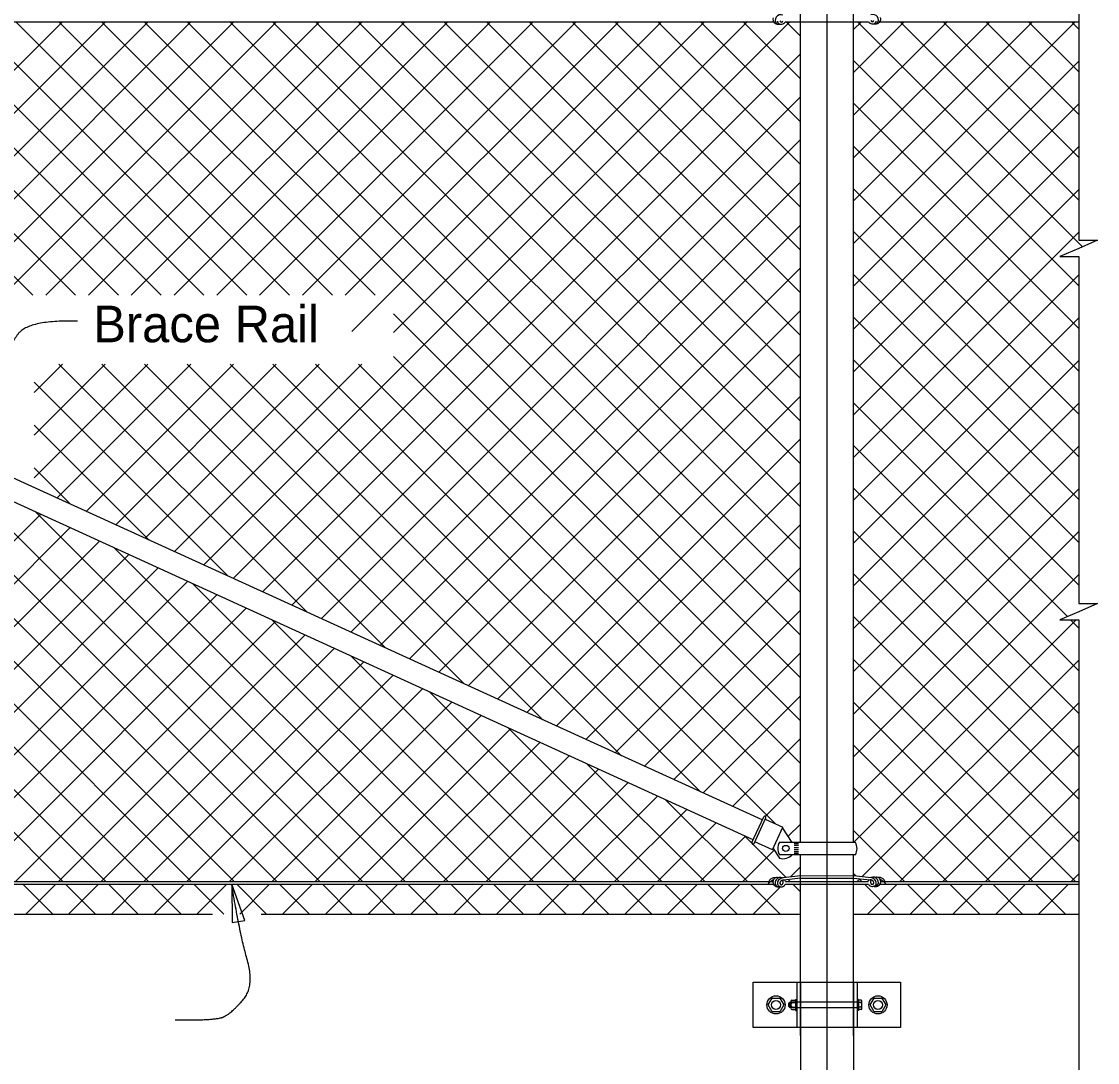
# Model space of a CAD drawing. Extents: x 0 to 41, y -96 to 25.
# Drawn here: x 10.89 to 16.81, y 14.82 to 20.56 of the extents above; entities that cross this region are included whole.
import ezdxf

# ---------------------------------------------------------------- set-up
doc = ezdxf.new("R2010")
doc.units = 0
for name, color, linetype in [('CL_Major', 7, 'Continuous'), ('Dimension', 7, 'Continuous'), ('Miscellaneous', 7, 'Continuous'), ('SteelMisc', 7, 'Continuous'), ('SteelMisc_h', 7, 'Continuous'), ('SupstrConc', 7, 'Continuous'), ('TextStructures', 7, 'Continuous')]:
    doc.layers.add(name, color=color, linetype=linetype)

msp = doc.modelspace()

# ---------------------------------------------------------------- linework, layer by layer
at = {"layer": 'CL_Major'}
msp.add_line((15.3237, 24.2317), (15.3237, 12.9956), dxfattribs=at)
at = {"layer": 'Dimension'}
for points in [[(16.7107, 22.5773), (16.7107, 19.3509), (16.814, 19.3509), (16.7107, 19.3059), (16.6074, 19.2609), (16.7107, 19.2609), (16.7107, 18.3673)], [(16.7107, 18.3673), (16.7107, 17.3495), (16.814, 17.3495), (16.7107, 17.3045), (16.6074, 17.2595), (16.7107, 17.2595), (16.7107, 15.0552)], [(16.7107, 15.3052), (16.7107, 13.4544), (16.814, 13.4544), (16.7107, 13.4094), (16.6074, 13.3644), (16.7107, 13.3644), (16.7107, 11.3636)]]:
    msp.add_lwpolyline(points, dxfattribs=at)
msp.add_lwpolyline([(12.0447, 15.8029), (12.0463, 15.5917), (12.1158, 15.604)], close=True, dxfattribs=at)
for points in [[(11.1949, 18.9047), (10.9254, 18.9129), (10.8073, 18.7544), (10.8043, 18.6333), (10.809, 18.4655), (10.817, 18.0525)], [(11.7334, 15.056), (11.9563, 15.0524), (12.0412, 15.0914), (12.172, 15.2401), (12.0871, 15.5375), (12.0447, 15.8029)]]:
    msp.add_open_spline(points, degree=2, dxfattribs=at)
at = {"layer": 'Miscellaneous'}
for p, q in [((9.3021, 18.7443), (11.113, 20.5552)), ((9.4413, 20.5552), (10.9489, 19.0476)), ((9.4639, 18.6704), (11.3487, 20.5552)), ((9.6257, 18.5965), (11.5844, 20.5552)), ((9.677, 20.5552), (11.1846, 19.0476)), ((9.7875, 18.5226), (11.8201, 20.5552)), ((9.9127, 20.5552), (11.4203, 19.0476)), ((9.9493, 18.4487), (12.0558, 20.5552)), ((10.1111, 18.3748), (12.2915, 20.5552)), ((10.1484, 20.5552), (11.656, 19.0476)), ((10.3841, 20.5552), (11.8917, 19.0476)), ((10.6198, 20.5552), (12.1274, 19.0476)), ((10.8555, 20.5552), (12.3631, 19.0476)), ((11.0197, 19.0476), (12.5272, 20.5552)), ((11.0912, 20.5552), (12.5988, 19.0476)), ((11.2554, 19.0476), (12.7629, 20.5552)), ((11.327, 20.5552), (12.8345, 19.0476)), ((11.4911, 19.0476), (12.9986, 20.5552)), ((11.5627, 20.5552), (13.26, 18.8579)), ((11.7268, 19.0476), (13.2343, 20.5552)), ((11.7984, 20.5552), (15.1779, 17.1756)), ((11.9625, 19.0476), (13.47, 20.5552)), ((12.0341, 20.5552), (15.1779, 17.4113)), ((12.1982, 19.0476), (13.7057, 20.5552)), ((12.2698, 20.5552), (15.1779, 17.6471)), ((12.4339, 19.0476), (13.9414, 20.5552)), ((12.5055, 20.5552), (15.1779, 17.8828)), ((12.6696, 19.0476), (14.1771, 20.5552)), ((12.706, 18.8484), (14.4129, 20.5552)), ((12.7412, 20.5552), (15.1779, 18.1185)), ((12.752, 18.1873), (15.12, 20.5552)), ((12.9357, 18.8424), (14.6486, 20.5552)), ((12.9769, 20.5552), (15.1779, 18.3542)), ((12.9878, 18.6587), (14.8843, 20.5552)), ((13.2126, 20.5552), (15.1779, 18.5899)), ((13.4483, 20.5552), (15.1779, 18.8256)), ((13.684, 20.5552), (15.1779, 19.0613)), ((13.9197, 20.5552), (15.1779, 19.297)), ((14.1554, 20.5552), (15.1779, 19.5327)), ((14.3911, 20.5552), (15.1779, 19.7684)), ((14.6268, 20.5552), (15.1779, 20.0041)), ((14.8625, 20.5552), (15.1779, 20.2398)), ((15.0982, 20.5552), (15.1779, 20.4755)), ((15.4696, 20.5115), (15.5133, 20.5552)), ((15.4696, 19.5686), (16.4561, 20.5552)), ((15.4696, 19.8043), (16.2204, 20.5552)), ((15.4696, 19.3329), (16.6918, 20.5552)), ((15.4696, 20.2758), (15.749, 20.5552)), ((15.4696, 20.0396), (15.9852, 20.5552)), ((15.4916, 20.5552), (16.7317, 19.315)), ((15.7273, 20.5552), (16.7107, 19.5718)), ((15.963, 20.5552), (16.7107, 19.8075)), ((16.1987, 20.5552), (16.7107, 20.0432)), ((16.4344, 20.5552), (16.7107, 20.2789)), ((16.6701, 20.5552), (16.7107, 20.5146)), ((12.9878, 18.1873), (15.1779, 20.3775)), ((15.4696, 20.3415), (16.7107, 19.1004)), ((15.4696, 19.0972), (16.7107, 20.3383)), ((13.2098, 18.1736), (15.1779, 20.1418)), ((15.4696, 20.1058), (16.7107, 18.8647)), ((15.4696, 18.8615), (16.7107, 20.1026)), ((13.4592, 18.1873), (15.1779, 19.9061)), ((15.4696, 19.8701), (16.7107, 18.629)), ((15.4696, 18.6258), (16.7107, 19.8669)), ((13.4803, 17.9727), (15.1779, 19.6704)), ((15.4696, 19.6344), (16.7107, 18.3933)), ((15.4696, 18.3901), (16.7107, 19.6312)), ((12.8619, 17.1187), (15.1779, 19.4347)), ((15.4696, 19.3987), (16.7107, 18.1576)), ((15.4696, 18.1544), (16.7107, 19.3955)), ((13.0237, 17.0448), (15.1779, 19.199)), ((15.4696, 19.163), (16.7107, 17.9219)), ((15.4696, 17.9187), (16.7107, 19.1598)), ((12.9357, 18.9464), (15.1779, 16.7042)), ((13.1856, 16.9709), (15.1779, 18.9632)), ((15.4696, 18.9273), (16.7107, 17.6862)), ((15.4696, 17.683), (16.7107, 18.9241)), ((13.26, 18.8579), (15.1779, 16.9399)), ((8.7959, 18.8436), (11.8219, 15.8177)), ((12.9357, 18.7107), (15.1779, 16.4685)), ((13.3474, 16.897), (15.1779, 18.7275)), ((15.4696, 18.6916), (16.7107, 17.4505)), ((15.4696, 17.4473), (16.7107, 18.6884)), ((9.2297, 18.6455), (12.0576, 15.8177)), ((10.9563, 18.0414), (11.583, 18.6681)), ((10.9563, 18.2771), (11.3473, 18.6681)), ((10.9563, 18.5128), (11.1116, 18.6681)), ((11.082, 17.9315), (11.8187, 18.6681)), ((11.0927, 18.6681), (12.4575, 17.3034)), ((11.2471, 17.8609), (12.0544, 18.6681)), ((11.3284, 18.6681), (12.8913, 17.1053)), ((11.4056, 17.7837), (12.2901, 18.6681)), ((11.5641, 18.6681), (13.325, 16.9072)), ((11.5674, 17.7098), (12.5258, 18.6681)), ((11.7293, 17.6359), (12.7615, 18.6681)), ((11.7998, 18.6681), (13.7588, 16.7091)), ((11.8911, 17.562), (12.9878, 18.6587)), ((12.0355, 18.6681), (14.1926, 16.511)), ((12.2712, 18.6681), (14.6264, 16.3129)), ((12.5069, 18.6681), (15.0396, 16.1355)), ((12.7426, 18.6681), (15.1779, 16.2328)), ((10.9563, 18.5689), (12.0237, 17.5015)), ((9.6635, 18.4474), (12.2933, 15.8177)), ((13.5092, 16.8231), (15.1779, 18.4918)), ((15.4696, 18.4559), (16.6482, 17.2773)), ((15.4696, 17.2116), (16.7107, 18.4527)), ((10.9563, 18.3332), (11.5899, 17.6996)), ((10.0973, 18.2494), (12.529, 15.8177)), ((13.671, 16.7492), (15.1779, 18.2561)), ((15.4696, 18.2202), (16.7107, 16.9791)), ((15.4696, 16.9759), (16.7107, 18.217)), ((12.0529, 17.4881), (12.752, 18.1873)), ((12.2147, 17.4142), (12.9878, 18.1873)), ((12.3765, 17.3403), (13.2098, 18.1736)), ((12.5383, 17.2665), (13.4592, 18.1873)), ((10.9563, 18.0975), (11.1561, 17.8976)), ((10.531, 18.0513), (12.7647, 15.8177)), ((13.8328, 16.6753), (15.1779, 18.0204)), ((12.7001, 17.1926), (13.4803, 17.9727)), ((15.4696, 17.9845), (16.7107, 16.7434)), ((15.4696, 16.7402), (16.7107, 17.9813)), ((10.9648, 17.8532), (13.0004, 15.8177)), ((8.9682, 15.8177), (10.9915, 17.841)), ((9.5734, 17.8305), (11.5862, 15.8177)), ((13.9946, 16.6014), (15.1779, 17.7847)), ((9.2039, 15.8177), (11.1534, 17.7671)), ((15.4696, 17.7488), (16.7107, 16.5077)), ((15.4696, 16.5045), (16.7107, 17.7456)), ((9.4396, 15.8177), (11.3152, 17.6932)), ((9.6753, 15.8177), (11.477, 17.6193)), ((11.3986, 17.6551), (13.2361, 15.8177)), ((9.5734, 17.5948), (11.3505, 15.8177)), ((14.1564, 16.5275), (15.1779, 17.549)), ((9.911, 15.8177), (11.6388, 17.5454)), ((15.4696, 17.5131), (16.7107, 16.272)), ((15.4696, 16.2688), (16.7107, 17.5099)), ((10.1467, 15.8177), (11.8006, 17.4716)), ((11.8324, 17.4571), (13.4718, 15.8177)), ((10.3824, 15.8177), (11.9624, 17.3977)), ((9.5734, 17.3591), (11.1147, 15.8177)), ((10.6181, 15.8177), (12.1242, 17.3238)), ((14.3182, 16.4537), (15.1779, 17.3133)), ((10.8538, 15.8177), (12.286, 17.2499)), ((12.2662, 17.259), (13.7075, 15.8177)), ((15.4696, 17.2774), (16.7107, 16.0363)), ((15.4696, 16.0331), (16.696, 17.2595)), ((16.6659, 17.2595), (16.7107, 17.2148)), ((11.0895, 15.8177), (12.4479, 17.176)), ((11.3252, 15.8177), (12.6097, 17.1021)), ((14.4801, 16.3798), (15.1779, 17.0776)), ((11.5609, 15.8177), (12.7715, 17.0282)), ((12.6999, 17.0609), (13.9432, 15.8177)), ((15.4696, 17.0417), (16.6936, 15.8177)), ((15.5183, 15.8462), (16.7107, 17.0385)), ((11.7966, 15.8177), (12.9333, 16.9543)), ((12.0323, 15.8177), (13.0951, 16.8804)), ((13.1337, 16.8628), (14.1789, 15.8177)), ((14.6419, 16.3059), (15.1779, 16.8419)), ((12.268, 15.8177), (13.2569, 16.8066)), ((15.4696, 16.8059), (16.4579, 15.8177)), ((15.7255, 15.8177), (16.7107, 16.8028)), ((12.5037, 15.8177), (13.4187, 16.7327)), ((12.7394, 15.8177), (13.5806, 16.6588)), ((13.5675, 16.6647), (14.4146, 15.8177)), ((14.8037, 16.232), (15.1779, 16.6062)), ((12.9751, 15.8177), (13.7424, 16.5849)), ((15.4696, 16.5702), (16.2222, 15.8177)), ((15.9612, 15.8177), (16.7107, 16.5671)), ((13.2108, 15.8177), (13.9042, 16.511)), ((13.4465, 15.8177), (14.066, 16.4371)), ((14.0013, 16.4667), (14.6503, 15.8177)), ((13.6822, 15.8177), (14.2278, 16.3632)), ((14.9851, 16.1777), (15.1779, 16.3705)), ((15.4696, 16.3345), (15.9865, 15.8177)), ((16.1969, 15.8177), (16.7107, 16.3314)), ((13.9179, 15.8177), (14.3896, 16.2893)), ((14.4351, 16.2686), (14.886, 15.8177)), ((14.1536, 15.8177), (14.5514, 16.2154)), ((14.3893, 15.8177), (14.7132, 16.1416)), ((15.109, 16.0659), (15.1779, 16.1348)), ((14.6251, 15.8177), (14.8751, 16.0677)), ((14.8688, 16.0705), (15.0984, 15.841)), ((15.4696, 16.0988), (15.7508, 15.8177)), ((16.4326, 15.8177), (16.7107, 16.0957)), ((14.8608, 15.8177), (15.0332, 15.9901)), ((15.1226, 15.8438), (15.1779, 15.8991)), ((15.1105, 15.8288), (15.1217, 15.8177)), ((15.4696, 15.8631), (15.4823, 15.8504)), ((15.4898, 15.8177), (15.5058, 15.8337)), ((15.4983, 15.8344), (15.5151, 15.8177)), ((16.6683, 15.8177), (16.7107, 15.86)), ((10.8938, 15.8029), (11.0583, 15.6384)), ((10.9103, 15.6384), (11.0748, 15.8029)), ((11.1295, 15.8029), (11.294, 15.6384)), ((11.146, 15.6384), (11.3105, 15.8029)), ((11.3652, 15.8029), (11.5297, 15.6384)), ((11.3817, 15.6384), (11.5462, 15.8029)), ((11.6009, 15.8029), (11.7654, 15.6384)), ((11.6174, 15.6384), (11.7819, 15.8029)), ((11.8366, 15.8029), (12.0011, 15.6384)), ((11.8531, 15.6384), (12.0176, 15.8029)), ((12.0723, 15.8029), (12.2368, 15.6384)), ((12.0888, 15.6384), (12.2533, 15.8029)), ((12.308, 15.8029), (12.4725, 15.6384)), ((12.3245, 15.6384), (12.489, 15.8029)), ((12.5437, 15.8029), (12.7082, 15.6384)), ((12.5602, 15.6384), (12.7247, 15.8029)), ((12.7794, 15.8029), (12.9439, 15.6384)), ((12.7959, 15.6384), (12.9604, 15.8029)), ((13.0151, 15.8029), (13.1796, 15.6384)), ((13.0316, 15.6384), (13.1961, 15.8029)), ((13.2508, 15.8029), (13.4153, 15.6384)), ((13.2673, 15.6384), (13.4318, 15.8029)), ((13.4865, 15.8029), (13.651, 15.6384)), ((13.503, 15.6384), (13.6675, 15.8029)), ((13.7222, 15.8029), (13.8867, 15.6384)), ((13.7387, 15.6384), (13.9032, 15.8029)), ((13.9579, 15.8029), (14.1224, 15.6384)), ((13.9744, 15.6384), (14.1389, 15.8029)), ((14.1936, 15.8029), (14.3581, 15.6384)), ((14.2101, 15.6384), (14.3746, 15.8029)), ((14.4293, 15.8029), (14.5938, 15.6384)), ((14.4458, 15.6384), (14.6103, 15.8029)), ((14.665, 15.8029), (14.8295, 15.6384)), ((14.6815, 15.6384), (14.846, 15.8029)), ((14.9007, 15.8029), (15.0652, 15.6384)), ((14.9172, 15.6384), (15.0682, 15.7894)), ((15.1364, 15.8029), (15.1779, 15.7614)), ((15.4696, 15.7974), (15.4751, 15.8029)), ((15.5298, 15.8029), (15.6943, 15.6384)), ((15.5463, 15.6384), (15.7108, 15.8029)), ((15.7655, 15.8029), (15.93, 15.6384)), ((15.782, 15.6384), (15.9465, 15.8029)), ((16.0012, 15.8029), (16.1657, 15.6384)), ((16.0177, 15.6384), (16.1822, 15.8029)), ((16.2369, 15.8029), (16.4014, 15.6384)), ((16.2534, 15.6384), (16.4179, 15.8029)), ((16.4726, 15.8029), (16.6371, 15.6384)), ((16.4891, 15.6384), (16.6536, 15.8029)), ((16.7083, 15.8029), (16.7107, 15.8006)), ((15.1162, 15.1316), (15.1162, 15.1437)), ((15.1219, 15.1316), (15.1219, 15.1437))]:
    msp.add_line(p, q, dxfattribs=at)
at = {"layer": 'SteelMisc'}
for p, q in [((15.1779, 16.0337), (15.1779, 22.5181)), ((15.4696, 16.0337), (15.4696, 22.5181)), ((5.6317, 20.5552), (15.0294, 20.5552)), ((15.0943, 20.5552), (15.1779, 20.5552)), ((15.4696, 20.5552), (15.5527, 20.5552)), ((15.6154, 20.5552), (16.7107, 20.5552)), ((14.9671, 16.1573), (5.7264, 20.3771)), ((14.9174, 16.0483), (5.6703, 20.2709)), ((14.9107, 16.0337), (14.9751, 16.1748)), ((14.9229, 16.0281), (14.9873, 16.1692)), ((14.9836, 16.1611), (15.0806, 16.1167)), ((15.024, 15.9927), (15.0806, 16.1167)), ((15.0786, 16.1123), (15.13, 16.0337)), ((15.024, 15.9927), (14.927, 16.037)), ((15.4809, 16.0337), (15.0612, 16.0337)), ((15.1436, 16.0275), (15.1671, 16.0275)), ((15.1436, 16.0177), (15.1671, 16.0177)), ((15.1436, 16.0059), (15.1671, 16.0059)), ((15.0271, 15.9994), (15.0618, 15.9463)), ((15.4808, 15.9659), (15.0612, 15.9659)), ((15.1436, 15.9941), (15.1671, 15.9941)), ((15.1436, 15.9833), (15.1671, 15.9833)), ((15.1436, 15.9737), (15.1671, 15.9737)), ((15.1779, 14.97), (15.1779, 15.9659)), ((15.4696, 14.97), (15.4696, 15.9659)), ((15.1779, 15.8503), (15.083, 15.8392)), ((15.1779, 15.8358), (15.0853, 15.8262)), ((15.1779, 15.8503), (15.4691, 15.852)), ((15.1779, 15.8358), (15.4691, 15.8374)), ((15.4691, 15.852), (15.5667, 15.8405)), ((15.4691, 15.8374), (15.5612, 15.828)), ((5.6317, 15.8029), (15.0294, 15.8029)), ((5.633, 15.8177), (15.0028, 15.8177)), ((15.0127, 15.8177), (15.0258, 15.8177)), ((15.0943, 15.8029), (15.1779, 15.8029)), ((15.0957, 15.8177), (15.1779, 15.8177)), ((15.4696, 15.8177), (15.55, 15.8177)), ((15.4696, 15.8029), (15.5526, 15.8029)), ((15.6154, 15.8029), (16.7107, 15.8029)), ((15.6203, 15.8177), (15.6356, 15.8177)), ((15.644, 15.8177), (16.7107, 15.8177)), ((14.9178, 15.2635), (15.7297, 15.2635)), ((14.9178, 15.0135), (14.9178, 15.2635)), ((15.1571, 15.2635), (15.1571, 15.0135)), ((15.4904, 15.2635), (15.4904, 15.0135)), ((15.7297, 15.2635), (15.7297, 15.0135)), ((15.1134, 15.1465), (15.119, 15.1531)), ((15.1134, 15.1288), (15.1134, 15.1465)), ((15.1134, 15.1288), (15.119, 15.1232)), ((15.119, 15.1531), (15.1255, 15.1531)), ((15.119, 15.1232), (15.119, 15.1531)), ((15.119, 15.1232), (15.1255, 15.1232)), ((15.1255, 15.1564), (15.1255, 15.1207)), ((15.1302, 15.1515), (15.1505, 15.1515)), ((15.1302, 15.1256), (15.1505, 15.1256)), ((15.1304, 15.1646), (15.1505, 15.1646)), ((15.1505, 15.1688), (15.1505, 15.1082)), ((15.1505, 15.1688), (15.1571, 15.1688)), ((15.1505, 15.1646), (15.1505, 15.1126)), ((15.4967, 15.1688), (15.4906, 15.1688)), ((15.4967, 15.1688), (15.4967, 15.1082)), ((15.5114, 15.1645), (15.4967, 15.1645)), ((15.5115, 15.1515), (15.4967, 15.1515)), ((15.5115, 15.1255), (15.4967, 15.1255)), ((15.5165, 15.1191), (15.5165, 15.158)), ((15.1305, 15.1126), (15.1505, 15.1126)), ((15.1505, 15.1082), (15.1571, 15.1082)), ((15.4967, 15.1082), (15.4906, 15.1082)), ((15.5114, 15.1125), (15.4967, 15.1125)), ((15.7297, 15.0135), (14.9178, 15.0135)), ((15.1779, 15.0135), (15.1779, 13.7635)), ((15.4696, 15.0135), (15.4696, 13.7635))]:
    msp.add_line(p, q, dxfattribs=at)
for points in [[(15.0211, 15.1761), (15.0644, 15.1761), (15.0861, 15.1385), (15.0644, 15.101), (15.0211, 15.101), (14.9994, 15.1385)], [(15.5831, 15.1761), (15.6264, 15.1761), (15.6481, 15.1385), (15.6264, 15.101), (15.5831, 15.101), (15.5614, 15.1385)]]:
    msp.add_lwpolyline(points, close=True, dxfattribs=at)
for centre, radius in [((15.0428, 15.1385), 0.05), ((15.6047, 15.1385), 0.05), ((15.0428, 15.1385), 0.025), ((15.6047, 15.1385), 0.025)]:
    msp.add_circle(centre, radius, dxfattribs=at)
for centre, radius, start, end in [((14.9814, 16.1721), 0.00673, 335.4599, 155.4599), ((14.9169, 16.0309), 0.00673, 155.4599, 335.4599), ((15.1321, 15.158), 0.00674, 104.48908, 254.18889), ((15.145, 15.1385), 0.0196, 138.62797, 221.37203), ((15.1321, 15.1191), 0.00673, 105.7823, 255.54039), ((15.5097, 15.158), 0.00673, 285.7823, 75.54039), ((15.5097, 15.1191), 0.00674, 284.48908, 74.18889), ((15.4968, 15.1385), 0.0196, 318.62797, 41.37203)]:
    msp.add_arc(centre, radius, start, end, dxfattribs=at)
for centre, major_axis, ratio, start_param, end_param in [((15.0507, 20.5677), (-0.0249, 0), 0.957868, 5.913851, 7.104804), ((15.0683, 20.5648), (0.0295, 0), 0.957868, 1.132635, 3.996184), ((15.5778, 20.5666), (-0.0295, 0), 0.957868, 2.287002, 5.15055), ((15.5955, 20.5694), (0.0249, 0), 0.957868, 5.476514, 6.65252), ((15.052, 20.5637), (0.0231, 0), 0.957868, 3.795406, 4.839145), ((15.0581, 20.558), (0.0206, -0.0021), 0.798607, 4.32653, 5.170153), ((15.0716, 20.558), (0.0206, -0.0021), 0.798607, 3.319436, 5.220153), ((15.0728, 20.5601), (-0.00795, 0), 0.957868, 0.039428, 2.999692), ((15.0642, 20.5767), (0.0391, 0), 0.957868, 5.134108, 5.41974), ((15.0713, 20.5647), (0.0251, 0), 0.957868, 5.531357, 5.877802), ((15.5748, 20.5665), (-0.0251, 0), 0.957868, 0.487549, 0.751829), ((15.5819, 20.5785), (-0.0391, 0), 0.957868, 0.863445, 1.149078), ((15.5734, 20.5619), (0.00795, 0), 0.957868, 3.283494, 6.243757), ((15.5745, 20.5597), (-0.0206, -0.0021), 0.798607, 1.063032, 2.96375), ((15.588, 20.5597), (-0.0206, -0.0021), 0.798607, 1.113032, 1.956656), ((15.5941, 20.5654), (-0.0231, 0), 0.957868, 1.44404, 2.503632), ((15.1304, 16), (-0.0776, 0), 0.957868, 5.810211, 6.75616), ((15.4118, 16), (0.0776, 0), 0.957868, 5.807767, 6.754779), ((15.0784, 16.0146), (0.0647, -0.0342), 0.957868, 4.95193, 6.02771), ((15.037, 15.8034), (0.0373, 0), 0.957868, 1.427863, 3.108042), ((15.0581, 15.7637), (-0.0724, 0), 0.957868, 5.133134, 5.652106), ((15.0495, 15.8179), (0.023, 0), 0.957868, 1.29026, 2.970541), ((15.0682, 15.8125), (0.0295, 0), 0.957868, 1.132635, 4.039556), ((15.0817, 15.8143), (-0.0303, -0.0108), 0.724765, 4.35367, 6.324556), ((15.5748, 15.8142), (-0.0251, 0), 0.957868, 5.633507, 6.136824), ((15.5593, 15.8031), (0.0259, 0), 0.957868, 0.636815, 1.505671), ((15.5778, 15.8143), (-0.0295, 0), 0.957868, 2.287002, 5.15055), ((15.5643, 15.8161), (0.0303, -0.0108), 0.724765, 6.241815, 8.075668), ((15.5966, 15.8196), (-0.023, 0), 0.957868, 3.312645, 5.0491), ((15.609, 15.8052), (-0.0373, 0), 0.957868, 3.175144, 4.855322), ((15.5879, 15.7655), (0.0724, 0), 0.957868, 0.631079, 1.150052), ((15.0506, 15.8154), (-0.0249, 0), 0.957868, 6.009018, 7.089857), ((15.052, 15.8114), (0.0231, 0), 0.957868, 3.779554, 4.879821), ((15.0581, 15.8057), (0.0206, -0.0021), 0.798607, 4.32653, 5.170153), ((15.0716, 15.8057), (0.0206, -0.0021), 0.798607, 3.333154, 5.220153), ((15.0784, 15.8102), (-0.0139, 0), 0.957868, 5.22362, 6.905413), ((15.0727, 15.8078), (-0.00795, 0), 0.957868, 6.140374, 9.314262), ((15.0868, 15.8014), (-0.0259, 0), 0.957868, 4.777514, 5.62749), ((15.071, 15.8136), (0.0119, 0), 0.957868, 5.725876, 7.416677), ((15.0642, 15.8244), (0.0391, 0), 0.957868, 5.082588, 5.41974), ((15.071, 15.8136), (0.0119, 0), 0.957868, 5.639684, 5.723117), ((15.0713, 15.8124), (0.0251, 0), 0.957868, 5.531357, 5.877802), ((15.0713, 15.8124), (0.0251, 0), 0.957868, 0.221743, 0.609214), ((15.5748, 15.8142), (-0.0251, 0), 0.957868, 0.487549, 0.751829), ((15.5818, 15.8262), (-0.0391, 0), 0.957868, 0.863445, 1.149078), ((15.575, 15.8154), (-0.0119, 0), 0.957868, 5.149694, 6.840495), ((15.575, 15.8154), (-0.0119, 0), 0.957868, 0.560069, 0.643501), ((15.5733, 15.8096), (0.00795, 0), 0.957868, 3.252108, 6.243757), ((15.5745, 15.8074), (-0.0206, -0.0021), 0.798607, 1.063032, 2.950031), ((15.5677, 15.812), (0.0139, 0), 0.957868, 5.660958, 6.743456), ((15.5879, 15.8074), (-0.0206, -0.0021), 0.798607, 1.113032, 1.956656), ((15.594, 15.8131), (-0.0231, 0), 0.957868, 1.403365, 2.503632), ((15.5954, 15.8171), (0.0249, 0), 0.957868, 5.476514, 6.557353)]:
    msp.add_ellipse(centre, major_axis=major_axis, ratio=ratio, start_param=start_param, end_param=end_param, dxfattribs=at)
msp.add_ellipse((15.0971, 16.0004), major_axis=(0.0178, 0), ratio=0.957868, dxfattribs=at)
at = {"layer": 'SteelMisc_h'}
for p, q in [((15.1779, 20.5552), (15.4696, 20.5552)), ((15.1779, 15.8177), (15.4696, 15.8177)), ((15.1779, 15.8029), (15.4696, 15.8029)), ((15.1779, 15.2635), (15.1779, 15.0135)), ((15.4696, 15.2635), (15.4696, 15.0135)), ((15.4904, 15.1531), (15.1255, 15.1531)), ((15.1255, 15.1232), (15.4904, 15.1232))]:
    msp.add_line(p, q, dxfattribs=at)
at = {"layer": 'SupstrConc'}
for p, q in [((5.4696, 15.6384), (11.9379, 15.6384)), ((12.2068, 15.6384), (15.1779, 15.6384)), ((15.4696, 15.6384), (16.7107, 15.6384))]:
    msp.add_line(p, q, dxfattribs=at)

# ---------------------------------------------------------------- texts
at = {"layer": 'TextStructures'}
msp.add_text('Brace Rail', height=0.2016, dxfattribs=at).set_placement((11.2814, 18.789))

doc.saveas('drawing.dxf')
